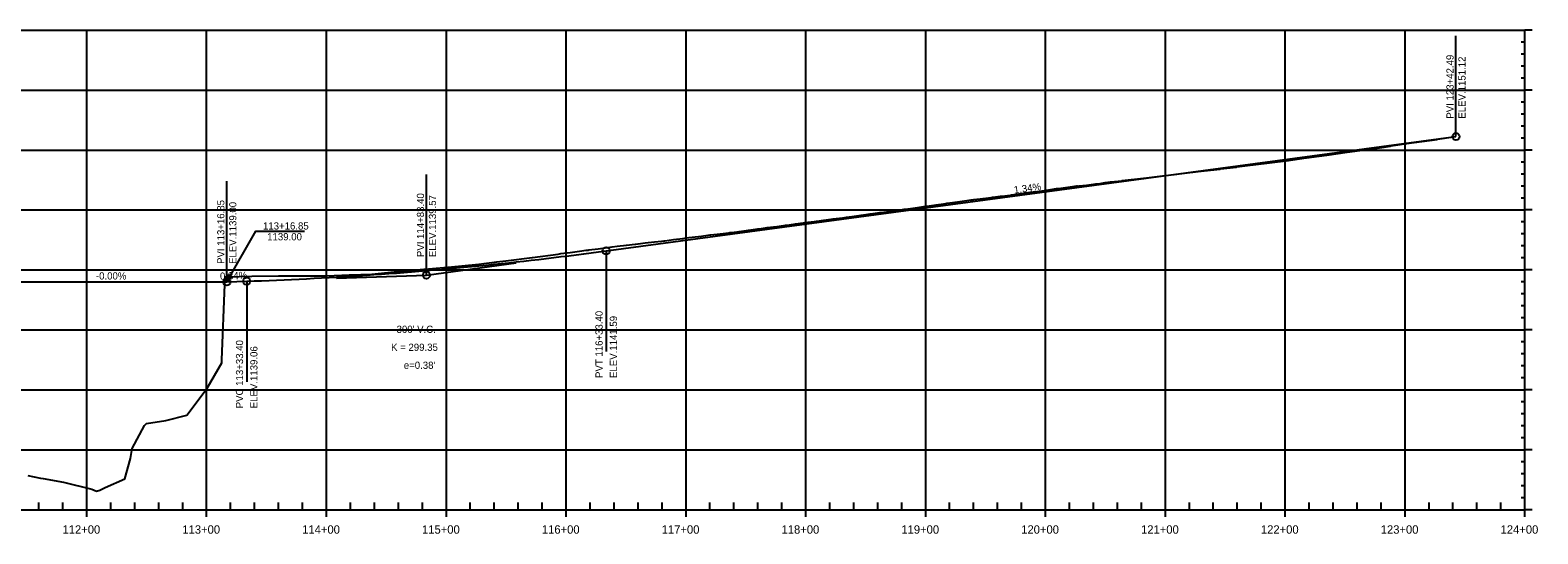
# Model space of a CAD drawing. Extents: x 688474 to 694748, y 765018 to 767373.
# Drawn here: x 692108 to 693366, y 766506 to 766926 of the extents above; entities that cross this region are included whole.
import ezdxf

# ---------------------------------------------------------------- set-up
doc = ezdxf.new("R2010")
doc.units = 0
for name, color, linetype in [('30', 7, 'Continuous'), ('37', 7, 'Continuous'), ('R_Exist Surface', 7, 'Continuous'), ('R_Horz Alg Annot', 7, 'Continuous'), ('R_Vert Alg', 7, 'Continuous'), ('R_Vert Alg Annot', 7, 'Continuous')]:
    doc.layers.add(name, color=color, linetype=linetype)

msp = doc.modelspace()

# ---------------------------------------------------------------- linework, layer by layer
at = {"layer": '37'}
for p, q in [((690955.2, 766926.5), (693355.2, 766926.5)), ((690955.2, 766926.5), (693355.2, 766926.5)), ((692155.2, 766526.5), (692155.2, 766926.5)), ((692255.2, 766526.5), (692255.2, 766926.5)), ((692355.2, 766526.5), (692355.2, 766926.5)), ((692455.2, 766526.5), (692455.2, 766926.5)), ((692555.2, 766526.5), (692555.2, 766926.5)), ((692655.2, 766526.5), (692655.2, 766926.5)), ((692755.2, 766526.5), (692755.2, 766926.5)), ((692855.2, 766526.5), (692855.2, 766926.5)), ((692955.2, 766526.5), (692955.2, 766926.5)), ((693055.2, 766526.5), (693055.2, 766926.5)), ((693155.2, 766526.5), (693155.2, 766926.5)), ((693255.2, 766526.5), (693255.2, 766926.5)), ((693355.2, 766526.5), (693355.2, 766926.5)), ((693361.2, 766926.5), (693355.2, 766926.5)), ((693361.2, 766926.5), (693355.2, 766926.5)), ((693355.2, 766916.5), (693352.2, 766916.5)), ((693355.2, 766906.5), (693352.2, 766906.5)), ((693355.2, 766896.5), (693352.2, 766896.5)), ((693355.2, 766886.5), (693352.2, 766886.5)), ((690955.2, 766876.5), (693355.2, 766876.5)), ((693361.2, 766876.5), (693355.2, 766876.5)), ((693355.2, 766866.5), (693352.2, 766866.5)), ((693355.2, 766856.5), (693352.2, 766856.5)), ((693355.2, 766846.5), (693352.2, 766846.5)), ((693355.2, 766836.5), (693352.2, 766836.5)), ((690955.2, 766826.5), (693355.2, 766826.5)), ((693361.2, 766826.5), (693355.2, 766826.5)), ((693355.2, 766816.5), (693352.2, 766816.5)), ((693355.2, 766806.5), (693352.2, 766806.5)), ((693355.2, 766796.5), (693352.2, 766796.5)), ((693355.2, 766786.5), (693352.2, 766786.5)), ((690955.2, 766776.5), (693355.2, 766776.5)), ((693361.2, 766776.5), (693355.2, 766776.5)), ((693355.2, 766766.5), (693352.2, 766766.5)), ((693355.2, 766756.5), (693352.2, 766756.5)), ((693355.2, 766746.5), (693352.2, 766746.5)), ((693355.2, 766736.5), (693352.2, 766736.5)), ((690955.2, 766726.5), (693355.2, 766726.5)), ((693361.2, 766726.5), (693355.2, 766726.5)), ((693355.2, 766716.5), (693352.2, 766716.5)), ((693355.2, 766706.5), (693352.2, 766706.5)), ((693355.2, 766696.5), (693352.2, 766696.5)), ((693355.2, 766686.5), (693352.2, 766686.5)), ((690955.2, 766676.5), (693355.2, 766676.5)), ((693361.2, 766676.5), (693355.2, 766676.5)), ((693355.2, 766666.5), (693352.2, 766666.5)), ((693355.2, 766656.5), (693352.2, 766656.5)), ((693355.2, 766646.5), (693352.2, 766646.5)), ((693355.2, 766636.5), (693352.2, 766636.5)), ((690955.2, 766626.5), (693355.2, 766626.5)), ((693361.2, 766626.5), (693355.2, 766626.5)), ((693355.2, 766616.5), (693352.2, 766616.5)), ((693355.2, 766606.5), (693352.2, 766606.5)), ((693355.2, 766596.5), (693352.2, 766596.5)), ((693355.2, 766586.5), (693352.2, 766586.5)), ((690955.2, 766576.5), (693355.2, 766576.5)), ((693361.2, 766576.5), (693355.2, 766576.5)), ((693355.2, 766566.5), (693352.2, 766566.5)), ((693355.2, 766556.5), (693352.2, 766556.5)), ((693355.2, 766546.5), (693352.2, 766546.5)), ((692115.2, 766526.5), (692115.2, 766532.5)), ((692135.2, 766526.5), (692135.2, 766532.5)), ((692175.2, 766526.5), (692175.2, 766532.5)), ((692195.2, 766526.5), (692195.2, 766532.5)), ((692215.2, 766526.5), (692215.2, 766532.5)), ((692235.2, 766526.5), (692235.2, 766532.5)), ((692275.2, 766526.5), (692275.2, 766532.5)), ((692295.2, 766526.5), (692295.2, 766532.5)), ((692315.2, 766526.5), (692315.2, 766532.5)), ((692335.2, 766526.5), (692335.2, 766532.5)), ((692375.2, 766526.5), (692375.2, 766532.5)), ((692395.2, 766526.5), (692395.2, 766532.5)), ((692415.2, 766526.5), (692415.2, 766532.5)), ((692435.2, 766526.5), (692435.2, 766532.5)), ((692475.2, 766526.5), (692475.2, 766532.5)), ((692495.2, 766526.5), (692495.2, 766532.5)), ((692515.2, 766526.5), (692515.2, 766532.5)), ((692535.2, 766526.5), (692535.2, 766532.5)), ((692575.2, 766526.5), (692575.2, 766532.5)), ((692595.2, 766526.5), (692595.2, 766532.5)), ((692615.2, 766526.5), (692615.2, 766532.5)), ((692635.2, 766526.5), (692635.2, 766532.5)), ((692675.2, 766526.5), (692675.2, 766532.5)), ((692695.2, 766526.5), (692695.2, 766532.5)), ((692715.2, 766526.5), (692715.2, 766532.5)), ((692735.2, 766526.5), (692735.2, 766532.5)), ((692775.2, 766526.5), (692775.2, 766532.5)), ((692795.2, 766526.5), (692795.2, 766532.5)), ((692815.2, 766526.5), (692815.2, 766532.5)), ((692835.2, 766526.5), (692835.2, 766532.5)), ((692875.2, 766526.5), (692875.2, 766532.5)), ((692895.2, 766526.5), (692895.2, 766532.5)), ((692915.2, 766526.5), (692915.2, 766532.5)), ((692935.2, 766526.5), (692935.2, 766532.5)), ((692975.2, 766526.5), (692975.2, 766532.5)), ((692995.2, 766526.5), (692995.2, 766532.5)), ((693015.2, 766526.5), (693015.2, 766532.5)), ((693035.2, 766526.5), (693035.2, 766532.5)), ((693075.2, 766526.5), (693075.2, 766532.5)), ((693095.2, 766526.5), (693095.2, 766532.5)), ((693115.2, 766526.5), (693115.2, 766532.5)), ((693135.2, 766526.5), (693135.2, 766532.5)), ((693175.2, 766526.5), (693175.2, 766532.5)), ((693195.2, 766526.5), (693195.2, 766532.5)), ((693215.2, 766526.5), (693215.2, 766532.5)), ((693235.2, 766526.5), (693235.2, 766532.5)), ((693275.2, 766526.5), (693275.2, 766532.5)), ((693295.2, 766526.5), (693295.2, 766532.5)), ((693315.2, 766526.5), (693315.2, 766532.5)), ((693335.2, 766526.5), (693335.2, 766532.5)), ((693355.2, 766536.5), (693352.2, 766536.5)), ((690955.2, 766526.5), (693355.2, 766526.5)), ((692155.2, 766520.5), (692155.2, 766526.5)), ((692255.2, 766520.5), (692255.2, 766526.5)), ((692355.2, 766520.5), (692355.2, 766526.5)), ((692455.2, 766520.5), (692455.2, 766526.5)), ((692555.2, 766520.5), (692555.2, 766526.5)), ((692655.2, 766520.5), (692655.2, 766526.5)), ((692755.2, 766520.5), (692755.2, 766526.5)), ((692855.2, 766520.5), (692855.2, 766526.5)), ((692955.2, 766520.5), (692955.2, 766526.5)), ((693055.2, 766520.5), (693055.2, 766526.5)), ((693155.2, 766520.5), (693155.2, 766526.5)), ((693255.2, 766520.5), (693255.2, 766526.5)), ((693361.2, 766526.5), (693355.2, 766526.5)), ((693355.2, 766520.5), (693355.2, 766526.5))]:
    msp.add_line(p, q, dxfattribs=at)
at = {"layer": 'R_Exist Surface'}
msp.add_line((692302.2, 766758.7), (692336.8, 766758.7), dxfattribs=at)
for points in [[(692106, 766555), (692116.5, 766552.9), (692118.8, 766552.6), (692135.8, 766549.4), (692159.4, 766543.7), (692163.4, 766542), (692166, 766542.9), (692170.6, 766544.9), (692186.8, 766552.3), (692191.7, 766569.1), (692193, 766577.5), (692203.2, 766596.8), (692205, 766598.5), (692221.2, 766600.9), (692238.6, 766605.3), (692255.5, 766627.8), (692267.9, 766649), (692267.9, 766651.4), (692270.5, 766714.4), (692270.7, 766720.8), (692270.7, 766720.8), (692272, 766720.8), (692292.8, 766721.2), (692292.9, 766721.2), (692315.1, 766721.6), (692335.2, 766721.6), (692335.2, 766721.6), (692335.3, 766721.6), (692355.4, 766721.7), (692355.5, 766721.7), (692374.2, 766722.4), (692374.4, 766722.4), (692393, 766723.1), (692414.2, 766725.1), (692414.7, 766725.1), (692415.2, 766725.2), (692436.5, 766727.2), (692437.2, 766727.2), (692459.5, 766729.2), (692482.2, 766731.2), (692482.4, 766731.2), (692497.3, 766733.2), (692504.8, 766734.1), (692526.7, 766736.8), (692527.2, 766736.9), (692548.5, 766739.7), (692549.6, 766739.9), (692550.7, 766740.1), (692550.7, 766740.1), (692558.5, 766741.1), (692566.3, 766742.1), (692572, 766742.9), (692573.5, 766743.1), (692574.2, 766743.2), (692582, 766744.2), (692589.8, 766745.2), (692593.6, 766745.7), (692597.7, 766746.2), (692605.5, 766747.2), (692612.8, 766748), (692613.3, 766748.1), (692615.2, 766748.4), (692621.2, 766749.1), (692629, 766749.9), (692634.8, 766750.5), (692636.8, 766750.8), (692637.4, 766750.9), (692644.7, 766751.8), (692652.5, 766752.8), (692655.6, 766753.2), (692657.8, 766753.6), (692660.3, 766753.9), (692668.2, 766754.8), (692673.3, 766755.4), (692675.3, 766755.7), (692676, 766755.8), (692683.8, 766756.7), (692690.8, 766757.5), (692691.7, 766757.6), (692692.7, 766757.7), (692695.4, 766758), (692699.5, 766758.6), (692707.3, 766759.7), (692715.2, 766760.8), (692715.5, 766760.8), (692717.9, 766761.1), (692723, 766761.8), (692730.9, 766762.8), (692738.3, 766763.8), (692738.7, 766763.8), (692739.2, 766763.9), (692746.5, 766764.9), (692751, 766765.5), (692751.8, 766765.6), (692754.4, 766766), (692762.2, 766767), (692763.7, 766767.2), (692764.4, 766767.3), (692770, 766768), (692776.3, 766768.9), (692776.8, 766768.9), (692777.9, 766769), (692785.7, 766770), (692789, 766770.5), (692789, 766770.5), (692789.1, 766770.5), (692793.5, 766771.1), (692801.4, 766772.2), (692808.8, 766773.2), (692808.9, 766773.2), (692809.2, 766773.2), (692817, 766774.3), (692817.8, 766774.4), (692824.9, 766775.3), (692828.4, 766775.7), (692828.7, 766775.7), (692828.7, 766775.7), (692832.7, 766776.4), (692837.2, 766777.1), (692837.2, 766777.1), (692837.3, 766777.1), (692840.5, 766777.6), (692848.4, 766778.7), (692855, 766779.7), (692855.2, 766779.7), (692856.2, 766779.8), (692864, 766780.9), (692871.9, 766782), (692872.7, 766782.1), (692873.1, 766782.1), (692879.7, 766783.1), (692887.5, 766784.1), (692893.2, 766784.9), (692894.4, 766785), (692894.4, 766785), (692895.4, 766785.2), (692903.2, 766786.2), (692909.9, 766787), (692911, 766787.1), (692915.8, 766787.7), (692915.8, 766787.7), (692917.3, 766787.9), (692917.6, 766788), (692918.9, 766788.1), (692925.6, 766788.9), (692925.9, 766789), (692926.7, 766789.1), (692934.5, 766790.2), (692942.4, 766791.3), (692945, 766791.6), (692945.6, 766791.7), (692950.2, 766792.3), (692958, 766793.4), (692964.4, 766794.3), (692965.9, 766794.5), (692973.7, 766795.6), (692981.2, 766796.7), (692981.3, 766796.7), (692981.5, 766796.7), (692982.5, 766796.5), (692983.3, 766796.6), (692989.4, 766797.3), (692997.2, 766798.3), (693000.7, 766798.7), (693005, 766799.4), (693009.3, 766800), (693009.6, 766800), (693018.8, 766800.9), (693019.2, 766801), (693036.9, 766803.1), (693037.1, 766803.1), (693052.9, 766805), (693053, 766805), (693062.5, 766806.2), (693068.9, 766806.9), (693069, 766806.9), (693084.9, 766808.8), (693085, 766808.8), (693100.9, 766810.6), (693101.1, 766810.7), (693114.6, 766812.3), (693114.8, 766812.4), (693128.3, 766814.1), (693128.5, 766814.1), (693142, 766815.8), (693142.2, 766815.8), (693155.7, 766817.5), (693156, 766817.5), (693172.7, 766819.9), (693173, 766819.9), (693189.8, 766822.2), (693190, 766822.3), (693206.8, 766824.6), (693207, 766824.6), (693223.9, 766827), (693224.1, 766827), (693237.7, 766828.9), (693242.8, 766829.8), (693243.3, 766829.9), (693243.3, 766829.9), (693262.6, 766832.7), (693262.8, 766832.7), (693282, 766835.4), (693282.4, 766835.5), (693297.7, 766837.7)], [(692272, 766716.5), (692296.2, 766758.7), (692302.2, 766758.7)]]:
    msp.add_lwpolyline(points, dxfattribs=at)
msp.add_lwpolyline([(692272, 766716.5), (692273.7, 766722.3), (692276.2, 766720.8)], close=True, dxfattribs=at)
at = {"layer": 'R_Vert Alg'}
for p, q in [((692588.6, 766742.4), (693297.7, 766837.7)), ((692363.6, 766719.6), (692438.6, 766722.2)), ((692438.6, 766722.2), (692513.6, 766732.3)), ((692087.2, 766716.5), (692272, 766716.5)), ((692272, 766716.5), (692288.6, 766717.1))]:
    msp.add_line(p, q, dxfattribs=at)
msp.add_lwpolyline([(692288.6, 766717.1), (692294.8, 766717.3), (692301.1, 766717.5), (692307.3, 766717.8), (692313.6, 766718), (692319.8, 766718.3), (692326.1, 766718.6), (692332.3, 766718.9), (692338.6, 766719.2), (692344.8, 766719.5), (692351.1, 766719.8), (692357.3, 766720.2), (692363.6, 766720.6), (692369.8, 766720.9), (692376.1, 766721.3), (692382.3, 766721.7), (692388.6, 766722.1), (692394.8, 766722.6), (692401.1, 766723), (692407.3, 766723.5), (692413.6, 766723.9), (692419.8, 766724.4), (692426.1, 766724.9), (692432.3, 766725.4), (692444.8, 766726.5), (692451.1, 766727), (692457.3, 766727.6), (692463.6, 766728.2), (692469.8, 766728.7), (692476.1, 766729.3), (692482.3, 766730), (692488.6, 766730.6), (692494.8, 766731.2), (692501.1, 766731.9), (692507.3, 766732.5), (692513.6, 766733.2), (692519.8, 766733.9), (692526.1, 766734.6), (692532.3, 766735.3), (692538.6, 766736.1), (692544.8, 766736.8), (692551.1, 766737.6), (692557.3, 766738.3), (692563.6, 766739.1), (692569.8, 766739.9), (692576.1, 766740.7), (692582.3, 766741.5), (692588.6, 766742.4)], dxfattribs=at)
for centre in [(693297.7, 766837.7), (692588.6, 766742.4), (692438.6, 766722.2), (692272, 766716.5), (692288.6, 766717.1)]:
    msp.add_circle(centre, 3, dxfattribs=at)
at = {"layer": 'R_Vert Alg Annot'}
for p, q in [((693297.7, 766837.7), (693297.7, 766921.7)), ((692272, 766716.5), (692272, 766800.5)), ((692438.6, 766722.2), (692438.6, 766806.2)), ((692588.6, 766742.4), (692588.6, 766658.4)), ((692288.6, 766717.1), (692288.6, 766633.1))]:
    msp.add_line(p, q, dxfattribs=at)

# ---------------------------------------------------------------- texts
at = {"layer": '30'}
for s, p in [('112+00', (692134.9, 766506.5)), ('113+00', (692234.9, 766506.5)), ('114+00', (692334.9, 766506.5)), ('115+00', (692434.9, 766506.5)), ('116+00', (692534.9, 766506.5)), ('117+00', (692634.9, 766506.5)), ('118+00', (692734.9, 766506.5)), ('119+00', (692834.9, 766506.5)), ('120+00', (692934.9, 766506.5)), ('121+00', (693034.9, 766506.5)), ('122+00', (693134.9, 766506.5)), ('123+00', (693234.9, 766506.5)), ('124+00', (693334.9, 766506.5))]:
    msp.add_text(s, height=7, dxfattribs=at).set_placement(p)
at = {"layer": 'R_Horz Alg Annot'}
for s, p in [('113+16.85', (692302.2, 766760.2)), ('1139.00', (692305.7, 766751.2))]:
    msp.add_text(s, height=6, dxfattribs=at).set_placement(p)
at = {"layer": 'R_Vert Alg Annot'}
for s, rotation, p in [('PVI 123+42.49', 90, (693295.7, 766852.7)), ('ELEV.1151.12', 90, (693305.7, 766852.7)), ('1.34%', 7.6581, (692929.2, 766790.2)), ('PVI 113+16.85', 90, (692270, 766731.5)), ('PVI 114+83.40', 90, (692436.6, 766737.2)), ('ELEV.1139.57', 90, (692446.6, 766737.2)), ('ELEV.1139.00', 90, (692280, 766731.5)), ('-0.00%', 360, (692162.8, 766718.5)), ('0.34%', 1.9613, (692266.4, 766718.3)), ('PVT 116+33.40', 90, (692585.6, 766636.4)), ('ELEV.1141.59', 90, (692597.6, 766636.4)), ('PVC 113+33.40', 90, (692285.6, 766611.1)), ('ELEV.1139.06', 90, (692297.6, 766611.1))]:
    msp.add_text(s, height=6, rotation=rotation, dxfattribs=at).set_placement(p)
for s, p in [("300' V.C.", (692413.7, 766674)), ('K = 299.35', (692409.1, 766659)), ("e=0.38'", (692419.7, 766644))]:
    msp.add_text(s, height=6, dxfattribs=at).set_placement(p)

doc.saveas('drawing.dxf')
